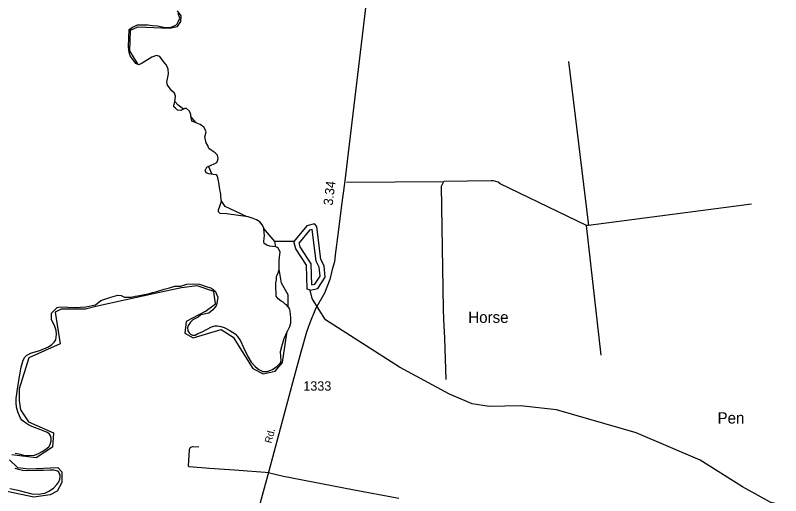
# Model space of a CAD drawing. Extents: x 2104537 to 2336408, y 34176 to 229611.
# Drawn here: x 2135938 to 2146100, y 134413 to 140787 of the extents above; entities that cross this region are included whole.
import ezdxf

# ---------------------------------------------------------------- set-up
doc = ezdxf.new("R2010")
doc.units = 0
for name, color, linetype in [('Exist Boundary Political CountyLine', 7, 'Continuous'), ('Exist Hydrographic Buffer Line', 7, 'Continuous'), ('Exist Hydrographic Creek Single Shore', 7, 'Continuous'), ('Exist Hydrographic Lake Shore', 7, 'Continuous'), ('Exist Hydrographic Misc Water Feature', 7, 'Continuous'), ('Exist Hydrographic River Shore', 7, 'Continuous'), ('Exist Hydrographic Swamp Label', 7, 'Continuous'), ('Exist Road Non-System Type 51', 7, 'Continuous'), ('Exist Road Secondary Mileage Hundredths English Label', 7, 'Continuous'), ('Exist Road Secondary Type 51 Attributed', 7, 'Continuous'), ('Exist Road Secondary Type 51 Label', 7, 'Continuous'), ('Exist Road Secondary Type 51 Number Label', 7, 'Continuous')]:
    doc.layers.add(name, color=color, linetype=linetype)

msp = doc.modelspace()

# ---------------------------------------------------------------- linework, layer by layer
at = {"layer": 'Exist Boundary Political CountyLine'}
for points in [[(2137491, 140214), (2137464, 140249), (2137451, 140295), (2137440, 140367), (2137445, 140494), (2137451, 140601), (2137495, 140632), (2137559, 140661), (2137696, 140662), (2137760, 140654), (2137825, 140646), (2137929, 140627), (2138007, 140632), (2138071, 140658), (2138088, 140673), (2138100, 140699), (2138121, 140751), (2138102, 140810)], [(2139589, 136862), (2139579, 136897), (2139541, 136945), (2139520, 136954), (2139495, 136981), (2139467, 136992), (2139429, 137023), (2139403, 137059), (2139401, 137101), (2139398, 137171), (2139399, 137237), (2139404, 137279), (2139408, 137320), (2139427, 137368), (2139441, 137415), (2139441, 137475), (2139441, 137525), (2139448, 137582), (2139453, 137646), (2139427, 137700), (2139399, 137715), (2139355, 137718), (2139317, 137726), (2139276, 137736), (2139241, 137760), (2139236, 137788), (2139243, 137829), (2139248, 137866), (2139244, 137902), (2139240, 137966), (2139215, 138008), (2139183, 138045), (2139142, 138074), (2139096, 138089), (2139031, 138112), (2138743, 138152), (2138658, 138159), (2138637, 138178), (2138637, 138206), (2138653, 138255), (2138675, 138320), (2138669, 138382), (2138666, 138413), (2138652, 138477), (2138648, 138508), (2138639, 138570), (2138622, 138655), (2138608, 138672), (2138566, 138675), (2138508, 138682), (2138473, 138696), (2138461, 138729), (2138480, 138774), (2138548, 138805), (2138568, 138811), (2138612, 138834), (2138623, 138857), (2138631, 138888), (2138623, 138933), (2138591, 138961), (2138538, 138998), (2138507, 139021), (2138493, 139059), (2138474, 139097), (2138456, 139176), (2138470, 139240), (2138458, 139273), (2138439, 139304), (2138392, 139339), (2138349, 139357), (2138317, 139370), (2138286, 139380), (2138272, 139421), (2138267, 139470), (2138251, 139516), (2138213, 139552), (2138189, 139551), (2138134, 139523), (2138092, 139530), (2138065, 139553), (2138043, 139571), (2138041, 139597), (2138054, 139641), (2138066, 139713), (2138051, 139753), (2138016, 139786), (2137957, 139861), (2137951, 139903), (2137959, 139943), (2137971, 140012), (2137966, 140074), (2137947, 140126), (2137902, 140181), (2137859, 140240), (2137814, 140254), (2137750, 140233), (2137624, 140154), (2137576, 140130), (2137539, 140150), (2137491, 140214)], [(2137476, 137045), (2137530, 137059), (2137560, 137065), (2137610, 137072), (2137719, 137098), (2137761, 137109), (2137817, 137124), (2137916, 137152), (2137985, 137173), (2138057, 137193), (2138134, 137194), (2138217, 137220), (2138301, 137222), (2138381, 137221), (2138410, 137213), (2138460, 137194), (2138543, 137166), (2138597, 137123), (2138609, 137087), (2138626, 137046), (2138619, 136995), (2138616, 136964), (2138603, 136931), (2138561, 136878), (2138508, 136836), (2138403, 136814), (2138365, 136781), (2138295, 136748), (2138265, 136716), (2138235, 136672), (2138225, 136640), (2138230, 136602), (2138246, 136574), (2138264, 136554), (2138292, 136544), (2138324, 136544), (2138362, 136563), (2138420, 136589), (2138486, 136624), (2138545, 136652), (2138593, 136665), (2138623, 136667), (2138669, 136657), (2138713, 136645), (2138788, 136606), (2138856, 136562), (2138890, 136527), (2138929, 136469), (2138969, 136381), (2139026, 136258), (2139071, 136184), (2139123, 136128), (2139173, 136089), (2139224, 136061), (2139284, 136060), (2139353, 136086), (2139415, 136133), (2139458, 136175), (2139469, 136207), (2139462, 136261), (2139460, 136327), (2139475, 136391), (2139506, 136497), (2139546, 136588), (2139581, 136658), (2139597, 136706), (2139596, 136774), (2139589, 136862)], [(2135936, 134979), (2135986, 134966), (2136047, 134951), (2136112, 134944), (2136192, 134951), (2136246, 134971), (2136294, 135001), (2136342, 135032), (2136382, 135062), (2136402, 135094), (2136412, 135142), (2136412, 135178), (2136404, 135205), (2136391, 135230), (2136367, 135251), (2136329, 135265), (2136265, 135291), (2136157, 135329), (2136112, 135354), (2136060, 135387), (2136026, 135416), (2136001, 135449), (2135973, 135527), (2135956, 135587), (2135949, 135646), (2135949, 135703), (2135961, 135794), (2135981, 135915), (2136017, 136120), (2136044, 136211), (2136065, 136249), (2136090, 136276), (2136155, 136309), (2136265, 136339), (2136377, 136387), (2136422, 136420), (2136452, 136450), (2136474, 136483), (2136482, 136518), (2136485, 136556), (2136479, 136603), (2136462, 136657), (2136420, 136749), (2136417, 136836), (2136440, 136859), (2136493, 136912), (2136540, 136921), (2136733, 136912), (2136875, 136921), (2137003, 136945), (2137074, 137002), (2137207, 137045), (2137298, 137073), (2137343, 137071), (2137390, 137047), (2137476, 137045)], [(2135866, 134508), (2135971, 134486), (2136157, 134438), (2136243, 134433), (2136329, 134448), (2136384, 134473), (2136447, 134514), (2136490, 134561), (2136517, 134597), (2136530, 134632), (2136535, 134662), (2136535, 134689), (2136522, 134712), (2136510, 134732), (2136487, 134743), (2136449, 134752), (2136399, 134752), (2136314, 134748), (2136220, 134747), (2136085, 134743), (2136032, 134747), (2135981, 134760), (2135936, 134775)]]:
    msp.add_lwpolyline(points, dxfattribs=at)
at = {"layer": 'Exist Hydrographic Buffer Line'}
for points in [[(2139877, 137211), (2139915, 137220), (2139986, 137328), (2139973, 137444), (2139932, 137527), (2139881, 137945), (2139846, 137937), (2139707, 137770)], [(2139877, 137211), (2139868, 137491), (2139722, 137714), (2139707, 137770)]]:
    msp.add_lwpolyline(points, dxfattribs=at)
at = {"layer": 'Exist Hydrographic Creek Single Shore'}
for points in [[(2139635, 137786), (2139585, 137786), (2139385, 137784)], [(2139974, 136879), (2139880, 137029), (2139855, 137138)], [(2151448, 130659), (2151308, 130921), (2151273, 131079), (2150997, 131495), (2150612, 131758), (2149911, 132172), (2148088, 133556), (2147412, 133979), (2146744, 134192), (2146427, 134215), (2145968, 134322), (2145593, 134530), (2145033, 134885), (2144181, 135246), (2143122, 135552), (2142646, 135607), (2142230, 135596), (2142004, 135630), (2141704, 135760), (2141037, 136118), (2140058, 136747), (2139974, 136879)]]:
    msp.add_lwpolyline(points, dxfattribs=at)
at = {"layer": 'Exist Hydrographic Lake Shore'}
for points in [[(2139855, 137138), (2139956, 137163), (2140054, 137311), (2140037, 137463), (2139996, 137546), (2139942, 137986), (2139909, 138020), (2139810, 137995), (2139635, 137786)], [(2139855, 137138), (2139813, 137152), (2139803, 137471), (2139661, 137687), (2139635, 137786)]]:
    msp.add_lwpolyline(points, dxfattribs=at)
at = {"layer": 'Exist Hydrographic Misc Water Feature'}
for points in [[(2138336, 139363), (2138270, 139445)], [(2139396, 137715), (2139385, 137784)]]:
    msp.add_lwpolyline(points, dxfattribs=at)
at = {"layer": 'Exist Hydrographic River Shore'}
for points in [[(2137568, 140135), (2137458, 140318), (2137468, 140591), (2137563, 140635), (2137987, 140615), (2138092, 140640), (2138136, 140706), (2138139, 140779), (2138090, 140846)], [(2138170, 139541), (2138102, 139594), (2138054, 139643)], [(2138550, 138677), (2138502, 138785)], [(2139015, 138114), (2138725, 138249), (2138673, 138332)], [(2139385, 137784), (2139240, 137960)], [(2139560, 136921), (2139563, 137078), (2139471, 137234), (2139443, 137419)], [(2138459, 136856), (2138596, 136957), (2138572, 137124), (2138352, 137197), (2138145, 137170), (2137813, 137102), (2137006, 136923), (2136869, 136886), (2136549, 136890), (2136469, 136850)], [(2136469, 136850), (2136534, 136429), (2136117, 136242), (2135990, 135831), (2135990, 135677)], [(2138459, 136856), (2138208, 136723), (2138188, 136569), (2138298, 136509), (2138672, 136616), (2138829, 136516), (2139090, 136102), (2139230, 136031), (2139387, 136065), (2139484, 136182), (2139549, 136594)], [(2135990, 135677), (2136006, 135551), (2136113, 135394), (2136444, 135247), (2136433, 135056), (2136217, 134916), (2135893, 134953)], [(2135860, 134889), (2135967, 134786), (2136117, 134769), (2136501, 134786), (2136557, 134729), (2136557, 134589), (2136494, 134474), (2136402, 134423), (2136185, 134395), (2135827, 134470)]]:
    msp.add_lwpolyline(points, dxfattribs=at)
at = {"layer": 'Exist Road Non-System Type 51'}
for p, q in [((2143281, 140175), (2143550, 137996)), ((2140336, 138573), (2141628, 138581)), ((2143550, 137996), (2143524, 137996)), ((2143716, 136276), (2143524, 137996))]:
    msp.add_line(p, q, dxfattribs=at)
for points in [[(2141659, 135955), (2141640, 136505), (2141626, 136755), (2141623, 136886), (2141597, 138518), (2141628, 138581)], [(2143524, 137996), (2142375, 138549), (2142348, 138573), (2142288, 138589), (2142256, 138591), (2141628, 138581)], [(2145712, 138280), (2145610, 138270), (2143550, 137996)], [(2139314, 134715), (2138847, 134751), (2138515, 134772), (2138245, 134794), (2138237, 134806), (2138251, 135022), (2138255, 135044), (2138267, 135058), (2138297, 135066), (2138377, 135059)], [(2139314, 134715), (2139498, 134673), (2140415, 134493), (2141032, 134380)]]:
    msp.add_lwpolyline(points, dxfattribs=at)
at = {"layer": 'Exist Road Secondary Type 51 Attributed'}
msp.add_lwpolyline([(2140772, 142446), (2140542, 140516), (2140308, 138556), (2140270, 138269), (2140225, 137909), (2140187, 137607), (2140175, 137514), (2140147, 137413), (2140113, 137282), (2140042, 137102), (2139924, 136893), (2139849, 136707), (2139804, 136583), (2139727, 136319), (2139637, 135978), (2139305, 134740), (2139141, 134142)], dxfattribs=at)

# ---------------------------------------------------------------- texts
at = {"layer": 'Exist Hydrographic Swamp Label'}
for s, p in [('Horse', (2141952, 136706)), ('Pen', (2145262, 135370))]:
    msp.add_text(s, height=150, dxfattribs=at).set_placement(p)
at = {"layer": 'Exist Road Secondary Mileage Hundredths English Label'}
msp.add_text('3.34', height=125, rotation=82.8289, dxfattribs=at).set_placement((2140151, 138258))
at = {"layer": 'Exist Road Secondary Type 51 Label'}
msp.add_text('Rd.', height=95, rotation=75.1551, dxfattribs=at).set_placement((2139338, 135102))
at = {"layer": 'Exist Road Secondary Type 51 Number Label'}
msp.add_text('1333', height=125, dxfattribs=at).set_placement((2139762, 135806))

doc.saveas('drawing.dxf')
